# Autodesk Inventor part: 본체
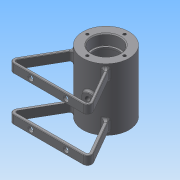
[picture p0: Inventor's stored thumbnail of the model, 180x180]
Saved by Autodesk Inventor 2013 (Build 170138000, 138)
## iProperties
Created: 2016-03
Part Number: 본체
Material: 일반
Document SubType Name: Modeling
Designer: Administrator
Density: 1 g/cm^3
Author: Administrator
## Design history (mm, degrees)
sketch "스케치1"
  geometry: C1 r 26 at (0, 0); 1 further point
  constraints: 1 centre point, 1 coincident
  dimensions: "d0" = 52 diameter of C1
extrude "돌출1" new body sketch "스케치1" stored distance "d1" = 70; taper "d2" = 0 deg
node "작업 평면1"
sketch "스케치2"
  geometry: L1 (0, 0)-(0, -62); L2 (-42.594, -62)-(42.594, -62); L3 (42.594, -62)-(0, 11.775); L4 (-42.594, -62)-(0, 11.775); C1 r 26 at (0, 0) reference; 1 further point
  constraints: 8 end point, 1 midpoint, 1 perpendicular, 1 vertical, 1 other
  dimensions: "d6" = 62 distance of L1.start L1.end; "d7" = 60 deg angle of L2 L3; "d8" = 85.18802 distance of L2.start L2.end
feature "리브1" sketch "스케치2" dims "d9" = 3, "d10" = 10, "d11" = 0, "d12" = 0, "d13" = 1, "d14" = 1
sketch "스케치3"
  geometry: C1 r 26 at (0, 0) reference; C2 r 21 at (0, 0); 1 further point
  constraints: 1 centre point, 1 coincident
  dimensions: "d15" = 42 diameter of C2
extrude "돌출2" cut sketch "스케치3" stored distance "d16" = 42; taper "d17" = 0 deg
sketch "스케치4"
  geometry: C1 r 26 at (0, 0) reference; C2 r 16 at (0, 0)
  constraints: 1 centre point, 1 coincident
  dimensions: "d18" = 32 diameter of C2
extrude "돌출3" cut sketch "스케치4" distance "d19" = 12; taper "d20" = 0 deg
sketch "스케치5"
  geometry: C1 r 16 at (0, 0) reference; C2 r 14 at (0, 0)
  constraints: 1 centre point, 1 coincident
  dimensions: "d21" = 28 diameter of C2
extrude "돌출4" cut sketch "스케치5" stored distance "d22" = 12; taper "d23" = 0 deg
node "작업 평면2"
sketch "스케치6"
  geometry: C1 r 5 at (0, 0); 1 further point
  constraints: 1 centre point, 1 coincident
  dimensions: "d25" = 10 diameter of C1
extrude "돌출5" join sketch "스케치6" stored distance "d26" = 12; taper "d27" = 0 deg
sketch "스케치7"
  geometry: L1 (-5, 25.515)-(-5, 29) reference; L2 (-5, 29)-(5, 29) reference; L3 (5, 29)-(5, 25.515) reference; L4 (0, 0)-(7.506, -28.012); L5 (0, 0)-(0, -50.543); C1 r 21 at (0, 0) reference; A1 r 26 centre (0, 0) between (-5, 25.515) and (5, 25.515) reference; 1 further point
  constraints: 4 end point, 1 parallel
  dimensions: "d28" = 29 distance of L4.start L4.end; "d29" = 15 deg angle of L4 L5
  node "절단 모서리 투영3"
node "작업 평면3"
sketch "스케치8"
  geometry: C1 r 6 at (0, 0); 1 further point
  constraints: 1 centre point, 1 coincident
  dimensions: "d30" = 12 diameter of C1
extrude "돌출6" join sketch "스케치8" stored distance "d31" = 12; taper "d32" = 0 deg
node "작업 평면4"
sketch "스케치9"
  geometry: L1 (-26, -35)-(-26, 35) reference; 2 further points
  constraints: 1 coincident, 1 other
feature "엠보싱1" sketch "스케치9" dims "d34" = 0.5, "d35" = 0
sketch "스케치10"
  geometry: C1 r 14 at (0, 0) reference; 1 further point
  constraints: 1 vertical alignment
  dimensions: "d36" = 21 distance of C1.centre point (0, 21)
hole "구멍1" sketch "스케치10" at (0, 21) diameter "d37" = 3.242; stored, may be unused: countersink angle "d41" = 90 deg, drill point angle "d43" = 118 deg; dims "d38" = 8, "d39" = 4, "d40" = 2, "d42" = 10
sketch "스케치11"
  geometry: C1 r 5 at (0, 0) reference
hole "구멍2" sketch "스케치11" at (0, 0) diameter "d47" = 5.188; stored, may be unused: countersink angle "d51" = 90 deg, drill point angle "d53" = 0 deg; dims "d48" = 50, "d49" = 4, "d50" = 2, "d52" = 10
sketch "스케치12"
  geometry: C1 r 6 at (0, 0) reference
hole "구멍3" sketch "스케치12" at (0, 0) diameter "d54" = 5.188; stored, may be unused: countersink angle "d58" = 90 deg, drill point angle "d60" = 0 deg; dims "d55" = 50, "d56" = 4, "d57" = 2, "d59" = 10
sketch "스케치13"
  geometry: 1 further point
fillet "모깎기1" dims "d61" = 3, "d62" = 0.3, "d63" = 5
fillet "모깎기2" dims "d64" = 2
sketch "스케치14"
  geometry: L1 (78.26, 0)-(0, 0) reference; L2 (0, 10)-(78.26, 10) reference; C1 r 3 at (19.13, 5); C2 r 3 at (59.13, 5); 1 further point
  constraints: 2 centre point
  dimensions: "d65" = 6 diameter of C1; "d66" = 6 diameter of C2; "d67" = 20 horizontal distance of point (39.13, -20) C1.centre; "d68" = 40 distance of C2.centre C1.centre; "d69" = 5 distance from line of C1.centre L2; "d70" = 5 distance from line of L1 C2.centre
extrude "돌출7" cut sketch "스케치14" stored distance "d71" = 12; taper "d72" = 0 deg
chamfer "모따기1" distance "d73" = 1; stored, may be unused: second distance "d74" = 2, angle "d75" = 45 deg
fillet "모깎기3" dims "d76" = 0.5
fillet "모깎기4" dims "d77" = 3
fillet "모깎기5" dims "d78" = 2
fillet "모깎기6" dims "d79" = 2
node "솔리드1"
mirror "대칭1"
pattern_circular "원형 패턴1" dims angle "d45" = 360 deg
mirror "대칭2"
mirror "대칭3"
mirror "대칭4"
node "절단 모서리 투영1"
node "절단 모서리 투영2"
other parameters: "d24" = 29, "d33" = -26
